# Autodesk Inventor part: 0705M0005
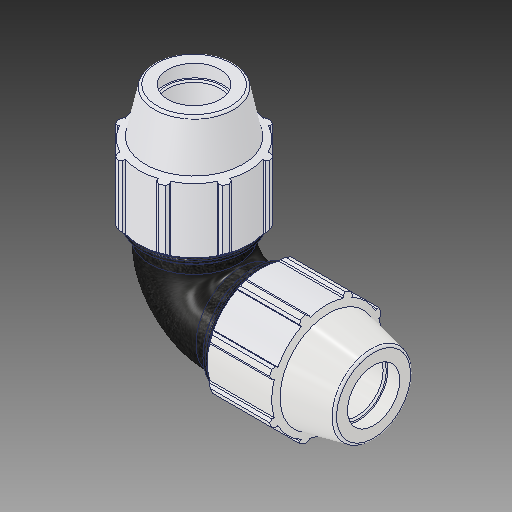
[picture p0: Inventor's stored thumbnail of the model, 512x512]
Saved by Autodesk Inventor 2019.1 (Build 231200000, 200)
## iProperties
Created: 2017-02
Part Number: 0705M0005
Material: PVC-Piping
Description: PLASSON 90° ELBOW 1/2'' - 1/2''
Document SubType Name: Modeling
Designer: KIM
Mass: 92.6774 g
Surface Area: 199.44 cm^2
Volume: 66.1981 cm^3
Density: 1.4 g/cm^3
Appearance: PTFE
Author: KIM
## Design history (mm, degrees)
derived "0705M0.ipt"
feature "Solid1::0705M0.ipt"
tag "TaggingFeature1"
body "Solid1"
other parameters: "d2" = 21.2, "d4" = 6.07483, "d5" = 18.2245, "d7" = 48.006, "d9" = 10.414, "d11" = 1.82245, "d13" = 120 deg, "d14" = 31.8, "d15" = 12 deg, "d16" = 41.76522, "d18" = 1.06, "d19" = 35 deg, "d20" = 17.5 deg, "d21" = 44.64558, "d23" = 0, "d25" = 360 deg, "d27" = 0.96012, "d33" = 0.424, "d42" = 26.97226, "d43" = 1.44018, "d46" = 0.636, "d51" = 72.898, "d59" = 90 deg, "d63" = 54.102, "d64" = 19.08, "d67" = 36.0045, "d68" = 1.82245, "d70" = 90 deg, "d_" = 21.2, "E_" = 48.006, "A_" = 72.898, "l_" = 54.102
